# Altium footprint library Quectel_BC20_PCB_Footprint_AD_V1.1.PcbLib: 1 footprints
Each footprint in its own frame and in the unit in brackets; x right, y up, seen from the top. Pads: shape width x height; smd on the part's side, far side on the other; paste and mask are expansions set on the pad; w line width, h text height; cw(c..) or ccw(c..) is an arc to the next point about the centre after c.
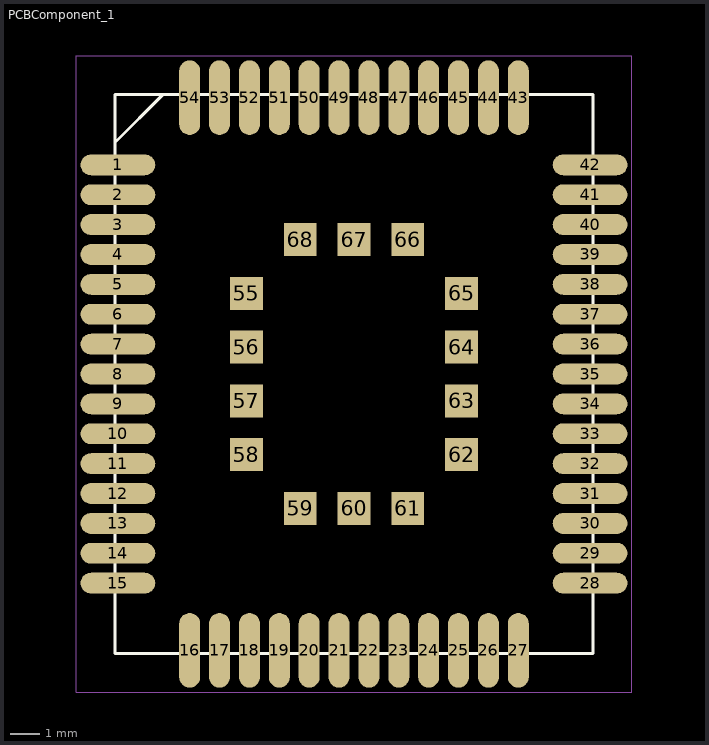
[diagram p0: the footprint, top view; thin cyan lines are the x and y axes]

## PCBComponent_1 [mm]
pads (68):
  oval 2.5x0.7 smd mask+0.05: 1(411.454,499.379) 2(411.454,498.379) 3(411.454,497.379) 4(411.454,496.379) 5(411.454,495.379) 6(411.454,494.379) 7(411.454,493.379) 8(411.454,492.379) 9(411.454,491.379) 10(411.454,490.379) 11(411.454,489.379) 12(411.454,488.379) 13(411.454,487.379) 14(411.454,486.379) 15(411.454,485.379) 28(427.254,485.379) 29(427.254,486.379) 30(427.254,487.379) 31(427.254,488.379) 32(427.254,489.379) 33(427.254,490.379) 34(427.254,491.379) 35(427.254,492.379) 36(427.254,493.379) 37(427.254,494.379) 38(427.254,495.379) 39(427.254,496.379) 40(427.254,497.379) 41(427.254,498.379) 42(427.254,499.379)
  oval 0.7x2.5 smd mask+0.05: 16(413.854,483.129) 17(414.854,483.129) 18(415.854,483.129) 19(416.854,483.129) 20(417.854,483.129) 21(418.854,483.129) 22(419.854,483.129) 23(420.854,483.129) 24(421.854,483.129) 25(422.854,483.129) 26(423.854,483.129) 27(424.854,483.129) 43(424.854,501.629) 44(423.854,501.629) 45(422.854,501.629) 46(421.854,501.629) 47(420.854,501.629) 48(419.854,501.629) 49(418.854,501.629) 50(417.854,501.629) 51(416.854,501.629) 52(415.854,501.629) 53(414.854,501.629) 54(413.854,501.629)
  rect 1.1x1.1 smd mask+0.05: 55(415.754,495.079) 56(415.754,493.279) 57(415.754,491.479) 58(415.754,489.679) 59(417.554,487.879) 60(419.354,487.879) 61(421.154,487.879) 62(422.954,489.679) 63(422.954,491.479) 64(422.954,493.279) 65(422.954,495.079) 66(421.154,496.879) 67(419.354,496.879) 68(417.554,496.879)
Top Overlay:
  lines w0.1: 411.354,500.129 412.954,501.729 ; 411.354,483.029 411.354,501.729 427.354,501.729 427.354,483.029 411.354,483.029
Mechanical 1:
  lines w0.01: 410.054,481.729 428.654,481.729 428.654,503.029 410.054,503.029 410.054,481.729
